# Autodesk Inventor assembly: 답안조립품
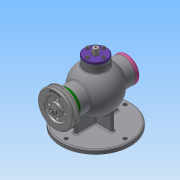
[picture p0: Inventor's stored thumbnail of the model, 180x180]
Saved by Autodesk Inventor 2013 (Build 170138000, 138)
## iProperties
Created: 2020-08
Part Number: 답안조립품
Document SubType Name: Assembly
Designer: 88
Author: 88
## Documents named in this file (18)
- C:\Users\88\Desktop\700806V1046\답안조립품.iam
- C:\Users\88\Desktop\700806V1046\본체.ipt
- C:\Users\88\Desktop\700806V1046\V-벨트풀리.ipt
- C:\Users\88\Desktop\700806V1046\너트 M8.ipt
- C:\Users\88\Desktop\700806V1046\뒤커버.ipt
- C:\Users\88\Desktop\700806V1046\멈춤링 15x1.ipt
- C:\Users\88\Desktop\700806V1046\멈춤링 35x1.6.ipt
- 멈춤링 35x1.6.ipt
- C:\Users\88\Desktop\700806V1046\베어링 6202.ipt
- 베어링 6202.ipt
- C:\Users\88\Desktop\700806V1046\볼트 M4.ipt
- C:\Users\88\Desktop\700806V1046\상부커버.ipt
- C:\Users\88\Desktop\700806V1046\슬라이드.ipt
- C:\Users\88\Desktop\700806V1046\앞커버.ipt
- C:\Users\88\Desktop\700806V1046\오일 실 15 30 7.ipt
- C:\Users\88\Desktop\700806V1046\칼라.ipt
- C:\Users\88\Desktop\700806V1046\키 3x3x12.ipt
- C:\Users\88\Desktop\700806V1046\편심축.ipt
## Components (1 placed, 1 different names)
1. V-벨트풀리:1
